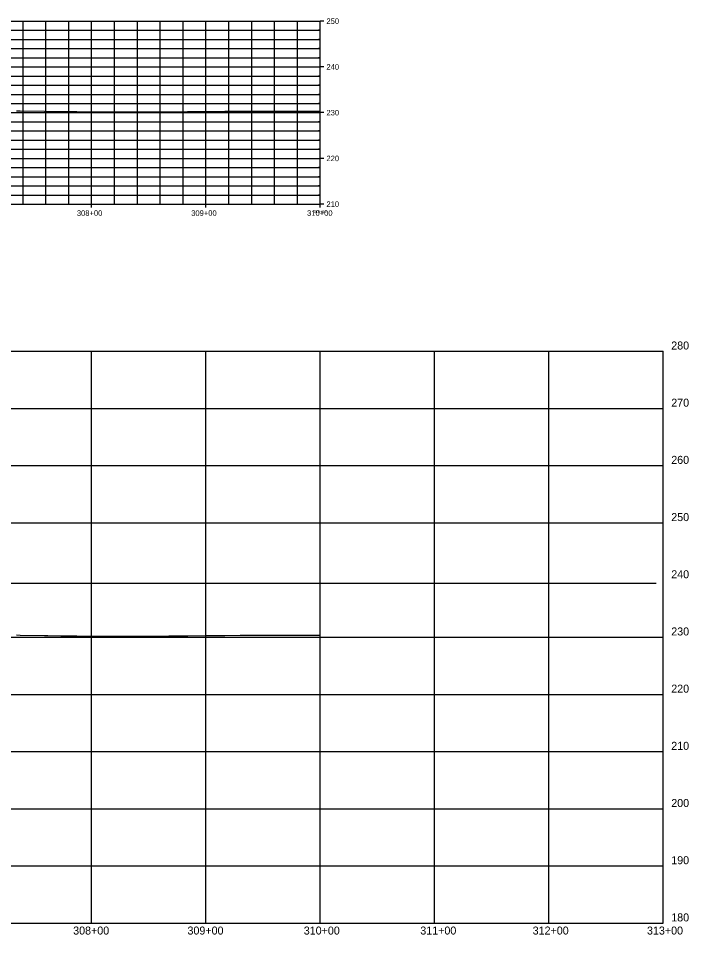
# Model space of a CAD drawing. Extents: x 1811793 to 1813336, y 532176 to 533566.
# Drawn here: x 1812750 to 1813336, y 532269 to 533070 of the extents above; entities that cross this region are included whole.
import ezdxf

# ---------------------------------------------------------------- set-up
doc = ezdxf.new("R2010")
doc.units = 0
for name, color, linetype in [('R_Axis', 7, 'Continuous'), ('R_Axis Annot', 7, 'Continuous'), ('R_Exist Surface', 7, 'Continuous'), ('R_Grid', 7, 'Continuous')]:
    doc.layers.add(name, color=color, linetype=linetype)

msp = doc.modelspace()

# ---------------------------------------------------------------- linework, layer by layer
at = {"layer": 'R_Axis'}
for p, q in [((1813014.24, 532907.89), (1813014.24, 533067.89)), ((1812014.24, 532907.89), (1813014.24, 532907.89)), ((1813314.24, 532279.32), (1813314.24, 532779.32)), ((1811814.24, 532279.32), (1813314.24, 532279.32))]:
    msp.add_line(p, q, dxfattribs=at)
at = {"layer": 'R_Exist Surface'}
for points in [[(1812748.61, 532989.44), (1812751.74, 532989.39), (1812772.9, 532989.08), (1812775.85, 532989.03), (1812787.25, 532988.93), (1812788.6, 532988.9), (1812800.16, 532988.81), (1812801.35, 532988.78), (1812813.08, 532988.68), (1812814.1, 532988.66), (1812826, 532988.57), (1812826.86, 532988.55), (1812839.85, 532988.59), (1812840.67, 532988.59), (1812853.78, 532988.63), (1812854.46, 532988.64), (1812867.71, 532988.68), (1812868.25, 532988.68), (1812881.64, 532988.73), (1812882.04, 532988.73), (1812897.99, 532988.84), (1812898.32, 532988.84), (1812914.39, 532988.96), (1812914.61, 532988.96), (1812930.8, 532989.08), (1812930.9, 532989.08), (1812944.3, 532989.17), (1812947.18, 532989.19), (1812947.2, 532989.19), (1812947.22, 532989.19), (1812953.47, 532989.21), (1812961.43, 532989.23), (1812961.45, 532989.23), (1812975.64, 532989.26), (1812975.7, 532989.26), (1812989.85, 532989.3), (1812989.96, 532989.3), (1813004.06, 532989.33), (1813004.21, 532989.33), (1813014.24, 532989.24)], [(1812748.61, 532531.26), (1812751.74, 532531.2), (1812772.9, 532530.8), (1812775.85, 532530.75), (1812787.25, 532530.63), (1812788.6, 532530.59), (1812800.16, 532530.47), (1812801.35, 532530.43), (1812813.08, 532530.31), (1812814.1, 532530.29), (1812826, 532530.17), (1812826.86, 532530.14), (1812839.85, 532530.19), (1812840.67, 532530.2), (1812853.78, 532530.25), (1812854.46, 532530.26), (1812867.71, 532530.31), (1812868.25, 532530.31), (1812881.64, 532530.37), (1812882.04, 532530.37), (1812897.99, 532530.51), (1812898.32, 532530.51), (1812914.39, 532530.66), (1812914.61, 532530.66), (1812930.8, 532530.81), (1812930.9, 532530.81), (1812944.3, 532530.93), (1812947.18, 532530.95), (1812947.2, 532530.95), (1812947.22, 532530.95), (1812953.47, 532530.97), (1812961.43, 532531), (1812961.45, 532531), (1812975.64, 532531.04), (1812975.7, 532531.04), (1812989.85, 532531.08), (1812989.96, 532531.08), (1813004.06, 532531.12), (1813004.21, 532531.12), (1813014.24, 532531.01)]]:
    msp.add_lwpolyline(points, dxfattribs=at)
at = {"layer": 'R_Grid'}
for p, q in [((1812014.24, 533067.89), (1813014.24, 533067.89)), ((1812014.24, 533067.89), (1813014.24, 533067.89)), ((1812754.24, 532907.89), (1812754.24, 533067.89)), ((1812774.24, 532907.89), (1812774.24, 533067.89)), ((1812794.24, 532907.89), (1812794.24, 533067.89)), ((1812814.24, 532907.89), (1812814.24, 533067.89)), ((1812834.24, 532907.89), (1812834.24, 533067.89)), ((1812854.24, 532907.89), (1812854.24, 533067.89)), ((1812874.24, 532907.89), (1812874.24, 533067.89)), ((1812894.24, 532907.89), (1812894.24, 533067.89)), ((1812914.24, 532907.89), (1812914.24, 533067.89)), ((1812934.24, 532907.89), (1812934.24, 533067.89)), ((1812954.24, 532907.89), (1812954.24, 533067.89)), ((1812974.24, 532907.89), (1812974.24, 533067.89)), ((1812994.24, 532907.89), (1812994.24, 533067.89)), ((1813017.24, 533067.89), (1813014.24, 533067.89)), ((1813017.24, 533067.89), (1813014.24, 533067.89)), ((1813014.24, 532907.89), (1813014.24, 533067.89)), ((1812014.24, 533059.89), (1813014.24, 533059.89)), ((1813014.24, 533059.89), (1813012.74, 533059.89)), ((1812014.24, 533051.89), (1813014.24, 533051.89)), ((1813014.24, 533051.89), (1813012.74, 533051.89)), ((1812014.24, 533043.89), (1813014.24, 533043.89)), ((1813014.24, 533043.89), (1813012.74, 533043.89)), ((1812014.24, 533035.89), (1813014.24, 533035.89)), ((1813014.24, 533035.89), (1813012.74, 533035.89)), ((1812014.24, 533027.89), (1813014.24, 533027.89)), ((1813017.24, 533027.89), (1813014.24, 533027.89)), ((1812014.24, 533019.89), (1813014.24, 533019.89)), ((1813014.24, 533019.89), (1813012.74, 533019.89)), ((1812014.24, 533011.89), (1813014.24, 533011.89)), ((1813014.24, 533011.89), (1813012.74, 533011.89)), ((1812014.24, 533003.89), (1813014.24, 533003.89)), ((1813014.24, 533003.89), (1813012.74, 533003.89)), ((1812014.24, 532995.89), (1813014.24, 532995.89)), ((1813014.24, 532995.89), (1813012.74, 532995.89)), ((1812014.24, 532987.89), (1813014.24, 532987.89)), ((1813017.24, 532987.89), (1813014.24, 532987.89)), ((1812014.24, 532979.89), (1813014.24, 532979.89)), ((1813014.24, 532979.89), (1813012.74, 532979.89)), ((1812014.24, 532971.89), (1813014.24, 532971.89)), ((1813014.24, 532971.89), (1813012.74, 532971.89)), ((1812014.24, 532963.89), (1813014.24, 532963.89)), ((1813014.24, 532963.89), (1813012.74, 532963.89)), ((1812014.24, 532955.89), (1813014.24, 532955.89)), ((1813014.24, 532955.89), (1813012.74, 532955.89)), ((1812014.24, 532947.89), (1813014.24, 532947.89)), ((1813017.24, 532947.89), (1813014.24, 532947.89)), ((1812014.24, 532939.89), (1813014.24, 532939.89)), ((1813014.24, 532939.89), (1813012.74, 532939.89)), ((1812014.24, 532931.89), (1813014.24, 532931.89)), ((1813014.24, 532931.89), (1813012.74, 532931.89)), ((1812014.24, 532923.89), (1813014.24, 532923.89)), ((1813014.24, 532923.89), (1813012.74, 532923.89)), ((1812014.24, 532915.89), (1813014.24, 532915.89)), ((1813014.24, 532915.89), (1813012.74, 532915.89)), ((1812814.24, 532904.89), (1812814.24, 532907.89)), ((1812914.24, 532904.89), (1812914.24, 532907.89)), ((1813017.24, 532907.89), (1813014.24, 532907.89)), ((1813014.24, 532904.89), (1813014.24, 532907.89)), ((1813014.24, 532904.89), (1813014.24, 532907.89)), ((1811814.24, 532779.32), (1813314.24, 532779.32)), ((1811814.24, 532779.32), (1813314.24, 532779.32)), ((1812814.24, 532279.32), (1812814.24, 532779.32)), ((1812914.24, 532279.32), (1812914.24, 532779.32)), ((1813014.24, 532279.32), (1813014.24, 532779.32)), ((1813114.24, 532279.32), (1813114.24, 532779.32)), ((1813214.24, 532279.32), (1813214.24, 532779.32)), ((1811814.24, 532729.32), (1813314.24, 532729.32)), ((1811814.24, 532679.32), (1813314.24, 532679.32)), ((1811814.24, 532629.32), (1813314.24, 532629.32)), ((1811808, 532576.42), (1813308, 532576.42)), ((1811814.24, 532529.32), (1813314.24, 532529.32)), ((1811814.24, 532479.32), (1813314.24, 532479.32)), ((1811814.24, 532429.32), (1813314.24, 532429.32)), ((1811814.24, 532379.32), (1813314.24, 532379.32)), ((1811814.24, 532329.32), (1813314.24, 532329.32))]:
    msp.add_line(p, q, dxfattribs=at)

# ---------------------------------------------------------------- texts
at = {"layer": 'R_Axis Annot'}
for s, height, p in [('250', 4.8, (1813019.64, 533065.49)), ('240', 4.8, (1813019.64, 533025.49)), ('230', 4.8, (1813019.64, 532985.49)), ('220', 4.8, (1813019.64, 532945.49)), ('210', 4.8, (1813019.64, 532905.49)), ('308+00', 4.8, (1812801.33, 532897.69)), ('309+00', 4.8, (1812901.33, 532897.69)), ('310+00', 4.8, (1813002.69, 532897.69)), ('310+00', 2.4, (1813008.46, 532900.09)), ('280', 7, (1813321.24, 532780.82)), ('280', 7, (1813321.24, 532780.82)), ('270', 7, (1813321.24, 532730.82)), ('260', 7, (1813321.24, 532680.82)), ('250', 7, (1813321.24, 532630.82)), ('240', 7, (1813321.24, 532580.82)), ('230', 7, (1813321.24, 532530.82)), ('220', 7, (1813321.24, 532480.82)), ('210', 7, (1813321.24, 532430.82)), ('200', 7, (1813321.24, 532380.82)), ('190', 7, (1813321.24, 532330.82)), ('180', 7, (1813321.24, 532280.82)), ('308+00', 7, (1812798.1, 532269.32)), ('309+00', 7, (1812898.1, 532269.32)), ('310+00', 7, (1812999.8, 532269.32)), ('311+00', 7, (1813101.74, 532269.32)), ('312+00', 7, (1813200.04, 532269.32)), ('313+00', 7, (1813300.04, 532269.32))]:
    msp.add_text(s, height=height, dxfattribs=at).set_placement(p)

doc.saveas('drawing.dxf')
